Omron CX-Programmer project NuevoProyecto (CX-Programmer 9.50)

# PLC NewPLC1: CP1L-E EM

## Program P6_2 (cyclic task 0)
Local symbols
CNT_igual_a_0 15.01 BOOL
CNT_igual_a_1 15.02 BOOL
CNT_igual_a_2 15.03 BOOL
Etapa_0 10.00 BOOL
Etapa_1 10.01 BOOL
Etapa_2 10.02 BOOL
Etapa_3 10.03 BOOL
Etapa_4 10.04 BOOL
Etapa_5 10.05 BOOL
Etapa_6 10.06 BOOL
Etapa_7 10.07 BOOL
FCP 0.04 BOOL
FSS 15.00 BOOL
KB 100.01 BOOL
KS 100.00 BOOL
P1 0.01 BOOL
P2 0.02 BOOL
PB 0.00 BOOL
S 0.03 BOOL

### Section Sección1_Programa_principal
; Programa principal (Etapas 0 ... 7)

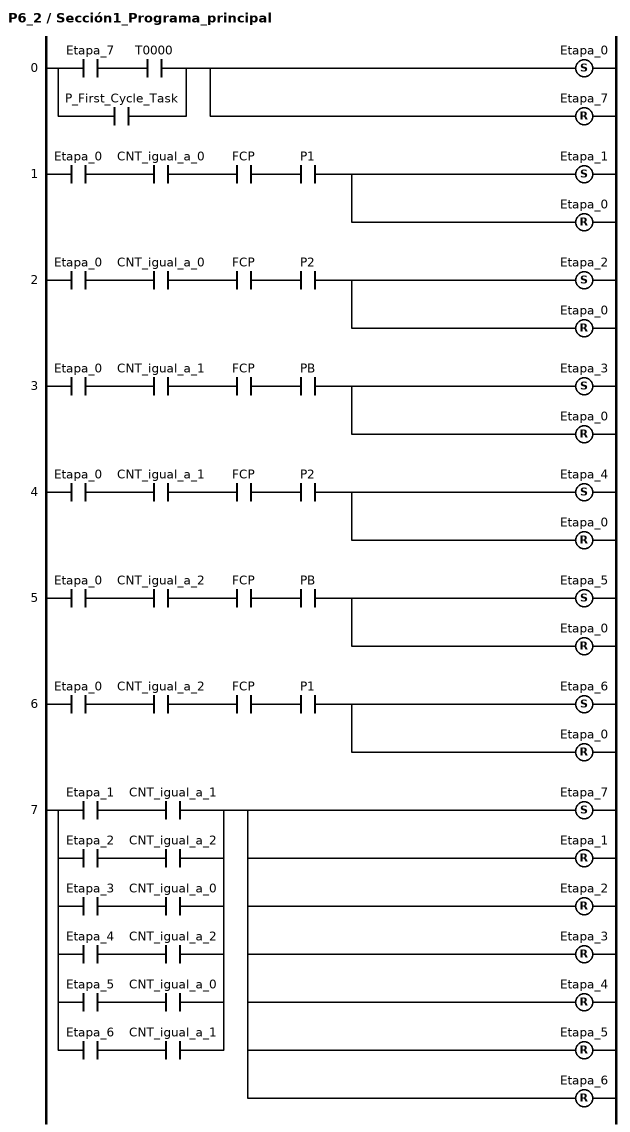
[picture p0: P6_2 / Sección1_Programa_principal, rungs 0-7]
; rung 0
LD Etapa_7
AND T0000
OR P_First_Cycle_Task
SET Etapa_0
RSET Etapa_7
; rung 1
LD Etapa_0
AND CNT_igual_a_0
AND FCP
AND P1
SET Etapa_1
RSET Etapa_0
; rung 2
LD Etapa_0
AND CNT_igual_a_0
AND FCP
AND P2
SET Etapa_2
RSET Etapa_0
; rung 3
LD Etapa_0
AND CNT_igual_a_1
AND FCP
AND PB
SET Etapa_3
RSET Etapa_0
; rung 4
LD Etapa_0
AND CNT_igual_a_1
AND FCP
AND P2
SET Etapa_4
RSET Etapa_0
; rung 5
LD Etapa_0
AND CNT_igual_a_2
AND FCP
AND PB
SET Etapa_5
RSET Etapa_0
; rung 6
LD Etapa_0
AND CNT_igual_a_2
AND FCP
AND P1
SET Etapa_6
RSET Etapa_0
; rung 7
LD Etapa_1
AND CNT_igual_a_1
LD Etapa_2
AND CNT_igual_a_2
ORLD
LD Etapa_3
AND CNT_igual_a_0
ORLD
LD Etapa_4
AND CNT_igual_a_2
ORLD
LD Etapa_5
AND CNT_igual_a_0
ORLD
LD Etapa_6
AND CNT_igual_a_1
ORLD
SET Etapa_7
RSET Etapa_1
RSET Etapa_2
RSET Etapa_3
RSET Etapa_4
RSET Etapa_5
RSET Etapa_6

### Section Sección2_Temporizador

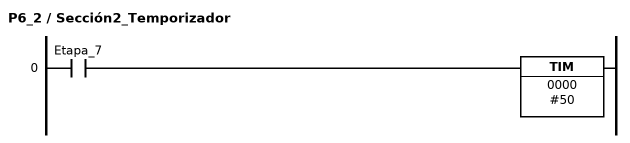
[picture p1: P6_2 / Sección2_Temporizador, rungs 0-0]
; rung 0
LD Etapa_7
TIM 0000 #50

### Section Sección3_Contador

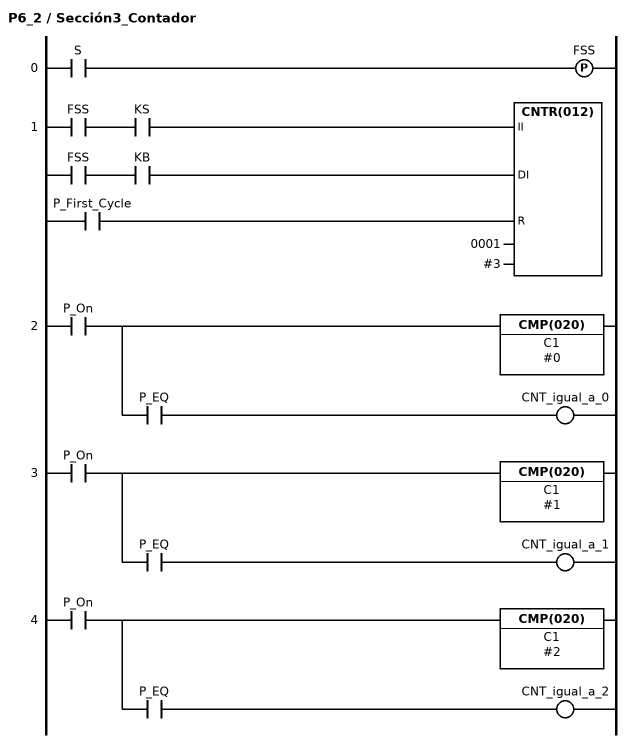
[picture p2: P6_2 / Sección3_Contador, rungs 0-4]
; rung 0
LD S
DIFU(013) FSS
; rung 1
LD FSS
AND KS
LD FSS
AND KB
LD P_First_Cycle
CNTR(012) 0001 #3
; rung 2
LD P_On
CMP(020) C1 #0
AND P_EQ
OUT CNT_igual_a_0
; rung 3
LD P_On
CMP(020) C1 #1
AND P_EQ
OUT CNT_igual_a_1
; rung 4
LD P_On
CMP(020) C1 #2
AND P_EQ
OUT CNT_igual_a_2

### Section Sección4_Salidas

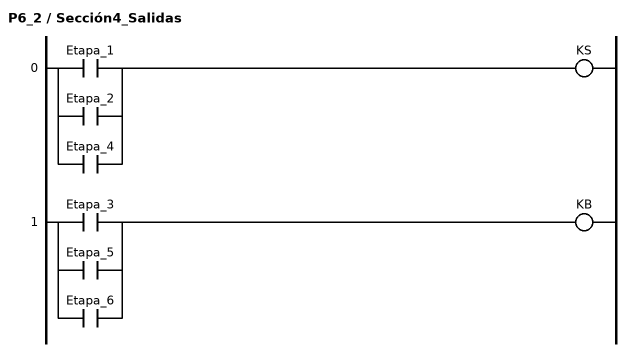
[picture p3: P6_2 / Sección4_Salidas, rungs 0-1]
; rung 0
LD Etapa_1
OR Etapa_2
OR Etapa_4
OUT KS
; rung 1
LD Etapa_3
OR Etapa_5
OR Etapa_6
OUT KB

### Section Sección5_END
; rung 0: Fin de programa
END(001)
